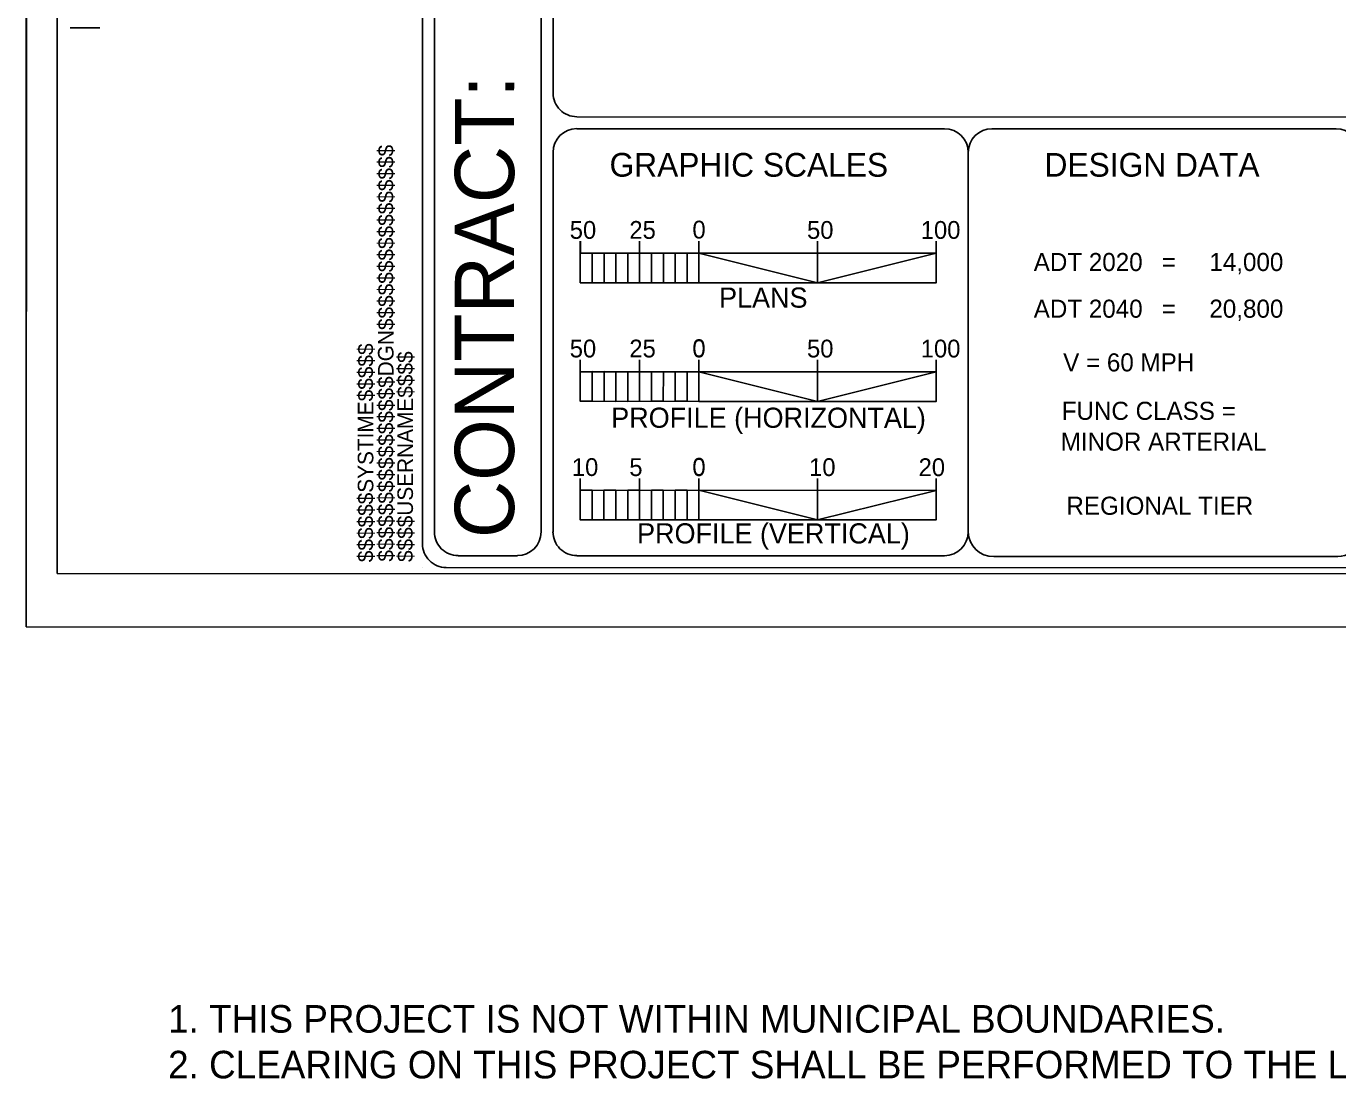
# Model space of a CAD drawing. Extents: x 2110629 to 2114002, y 669321 to 671542.
# Drawn here: x 2110629 to 2111580, y 669321 to 670084 of the extents above; entities that cross this region are included whole.
import ezdxf

# ---------------------------------------------------------------- set-up
doc = ezdxf.new("R2010")
doc.units = 0
for name, color, linetype in [('Exist Guardrail', 7, 'Continuous'), ('Exist Roads Curbs', 7, 'Continuous'), ('Exist Roads EOP Other Text', 7, 'Continuous'), ('Exist Structure Minor Catch Basin', 7, 'Continuous'), ('Exist Utilities Telephone Test Hole SUE LOS A Text', 7, 'Continuous'), ('Exist Utilities Water Test Hole SUE LOS A Text', 7, 'Continuous')]:
    doc.layers.add(name, color=color, linetype=linetype)

msp = doc.modelspace()

# ---------------------------------------------------------------- linework, layer by layer
at = {"layer": 'Exist Roads Curbs'}
for p, q in [((2110629.24, 671542.03), (2110628.92, 669648.68)), ((2110628.92, 669648.68), (2113527.5, 669648.19))]:
    msp.add_line(p, q, dxfattribs=at)
at = {"layer": 'Exist Roads EOP Other Text'}
msp.add_lwpolyline([(2110651.3, 669687.3), (2113519.77, 669686.81), (2113520.07, 671502.9), (2110651.61, 671503.39)], close=True, dxfattribs=at)
at = {"layer": 'Exist Structure Minor Catch Basin'}
for p, q in [((2111002.44, 669717.47), (2111002.74, 671473.14)), ((2111011.1, 670035.9), (2111011.35, 671473.14)), ((2110660.84, 670083.27), (2110682.35, 670083.29)), ((2110660.84, 670083.27), (2110682.35, 670083.29)), ((2111028.31, 670018.68), (2113472.49, 670018.27)), ((2111028.31, 670010.05), (2111295.1, 670010.03)), ((2111329.53, 670010), (2111579.11, 670009.98)), ((2111011.07, 669717.44), (2111011.1, 669992.86)), ((2111312.31, 669992.81), (2111312.27, 669717.39)), ((2111030.88, 669919.88), (2111030.88, 669928.47)), ((2111030.88, 669928.47), (2111030.88, 669928.47)), ((2111073.91, 669919.85), (2111073.91, 669928.48)), ((2111116.94, 669919.84), (2111116.94, 669928.45)), ((2111203, 669919.85), (2111203, 669928.44)), ((2111289.06, 669919.84), (2111289.07, 669928.44)), ((2111030.88, 669919.88), (2111030.87, 669898.36)), ((2111030.88, 669919.88), (2111030.88, 669919.88)), ((2111289.06, 669919.84), (2111030.88, 669919.88)), ((2111091.12, 669919.87), (2111091.12, 669898.35)), ((2111203, 669919.85), (2111203, 669898.34)), ((2111289.06, 669898.3), (2111289.06, 669919.84)), ((2111030.87, 669898.36), (2111289.06, 669898.3)), ((2111030.86, 669833.8), (2111030.86, 669842.42)), ((2111030.86, 669833.8), (2111030.86, 669842.42)), ((2111030.86, 669842.42), (2111030.86, 669842.42)), ((2111073.92, 669833.79), (2111073.9, 669842.42)), ((2111073.92, 669833.79), (2111073.9, 669842.42)), ((2111116.93, 669833.8), (2111116.93, 669842.39)), ((2111116.93, 669833.8), (2111116.93, 669842.39)), ((2111202.99, 669833.79), (2111202.99, 669842.4)), ((2111202.99, 669833.79), (2111202.99, 669842.4)), ((2111289.05, 669833.77), (2111289.07, 669842.38)), ((2111289.05, 669833.77), (2111289.07, 669842.38)), ((2111030.86, 669833.8), (2111030.86, 669812.3)), ((2111030.86, 669833.8), (2111030.86, 669833.8)), ((2111289.05, 669833.77), (2111030.86, 669833.8)), ((2111030.86, 669833.8), (2111030.86, 669833.8)), ((2111289.05, 669833.77), (2111030.86, 669833.8)), ((2111091.11, 669833.79), (2111091.1, 669812.29)), ((2111202.99, 669833.79), (2111202.98, 669812.27)), ((2111289.05, 669812.26), (2111289.05, 669833.77)), ((2111030.86, 669812.3), (2111289.05, 669812.26)), ((2111030.87, 669747.73), (2111030.85, 669756.36)), ((2111030.87, 669747.73), (2111030.85, 669756.36)), ((2111030.87, 669747.73), (2111030.85, 669756.36)), ((2111030.85, 669756.36), (2111030.85, 669756.36)), ((2111073.88, 669747.75), (2111073.88, 669756.33)), ((2111073.88, 669747.75), (2111073.88, 669756.33)), ((2111073.88, 669747.75), (2111073.88, 669756.33)), ((2111116.91, 669747.74), (2111116.93, 669756.33)), ((2111116.91, 669747.74), (2111116.93, 669756.33)), ((2111116.91, 669747.74), (2111116.93, 669756.33)), ((2111202.97, 669747.7), (2111202.97, 669756.33)), ((2111202.97, 669747.7), (2111202.97, 669756.33)), ((2111202.97, 669747.7), (2111202.97, 669756.33)), ((2111289.04, 669747.71), (2111289.04, 669756.3)), ((2111289.04, 669747.71), (2111289.04, 669756.3)), ((2111289.04, 669747.71), (2111289.04, 669756.3)), ((2111030.87, 669747.73), (2111030.84, 669726.24)), ((2111030.87, 669747.73), (2111030.87, 669747.73)), ((2111289.04, 669747.71), (2111030.87, 669747.73)), ((2111030.87, 669747.73), (2111030.87, 669747.73)), ((2111289.04, 669747.71), (2111030.87, 669747.73)), ((2111030.87, 669747.73), (2111030.87, 669747.73)), ((2111289.04, 669747.71), (2111030.87, 669747.73)), ((2111091.09, 669747.72), (2111091.09, 669726.21)), ((2111202.97, 669747.7), (2111202.97, 669726.19)), ((2111289.03, 669726.2), (2111289.04, 669747.71)), ((2111030.84, 669726.24), (2111289.03, 669726.2)), ((2110916.38, 669691.66), (2110916.38, 669691.66)), ((2110916.38, 669691.66), (2110916.38, 669691.66)), ((2110916.38, 669691.66), (2110916.38, 669691.66)), ((2110916.38, 669691.66), (2110916.38, 669691.66))]:
    msp.add_line(p, q, dxfattribs=at)
for points in [[(2110916.68, 671481.76), (2110916.38, 669708.87)], [(2110916.68, 671481.76), (2110916.38, 669708.87)], [(2110925.3, 671473.15), (2110924.99, 669717.48)], [(2110942.17, 669700.26), (2110985.23, 669700.26)], [(2111028.26, 669700.23), (2111295.05, 669700.2)], [(2111330.8, 669699.73), (2111580.38, 669699.68)], [(2110933.59, 669691.64), (2113481.04, 669691.21)]]:
    msp.add_lwpolyline(points, dxfattribs=at)
for points in [[(2111030.88, 669919.88), (2111039.48, 669919.88), (2111039.48, 669898.36), (2111030.87, 669898.36)], [(2111048.09, 669919.88), (2111056.7, 669919.85), (2111056.69, 669898.34), (2111048.11, 669898.34)], [(2111065.3, 669919.85), (2111073.91, 669919.85), (2111073.9, 669898.36), (2111065.3, 669898.36)], [(2111082.51, 669919.85), (2111091.12, 669919.87), (2111091.12, 669898.35), (2111082.51, 669898.36)], [(2111099.73, 669919.87), (2111108.33, 669919.87), (2111108.33, 669898.33), (2111099.72, 669898.35)], [(2111116.94, 669919.84), (2111203, 669898.34), (2111116.94, 669898.33)], [(2111289.06, 669919.84), (2111203, 669898.34), (2111289.06, 669898.3)], [(2111030.86, 669833.8), (2111039.47, 669833.82), (2111039.47, 669812.3), (2111030.86, 669812.3)], [(2111048.08, 669833.82), (2111056.68, 669833.81), (2111056.7, 669812.28), (2111048.07, 669812.3)], [(2111065.29, 669833.81), (2111073.92, 669833.79), (2111073.89, 669812.3), (2111065.28, 669812.28)], [(2111082.5, 669833.79), (2111091.11, 669833.79), (2111091.1, 669812.29), (2111082.5, 669812.29)], [(2111099.71, 669833.81), (2111108.32, 669833.81), (2111108.32, 669812.29), (2111099.71, 669812.29)], [(2111116.93, 669833.8), (2111202.98, 669812.27), (2111116.92, 669812.27)], [(2111289.05, 669833.77), (2111202.98, 669812.27), (2111289.05, 669812.26)], [(2111030.87, 669747.73), (2111039.45, 669747.73), (2111039.45, 669726.22), (2111030.84, 669726.24)], [(2111048.06, 669747.75), (2111056.67, 669747.75), (2111056.66, 669726.24), (2111048.06, 669726.24)], [(2111065.27, 669747.75), (2111073.88, 669747.75), (2111073.88, 669726.21), (2111065.27, 669726.23)], [(2111082.51, 669747.73), (2111091.09, 669747.72), (2111091.09, 669726.21), (2111082.48, 669726.23)], [(2111099.7, 669747.72), (2111108.3, 669747.74), (2111108.3, 669726.23), (2111099.69, 669726.23)], [(2111116.91, 669747.74), (2111202.97, 669726.19), (2111116.91, 669726.23)], [(2111289.04, 669747.71), (2111202.97, 669726.19), (2111289.03, 669726.2)]]:
    msp.add_lwpolyline(points, close=True, dxfattribs=at)
for centre, radius, start, end in [((2111028.32, 670035.97), 17.21, 179.9903, 269.9903), ((2111028.31, 669992.94), 17.21, 89.9903, 179.9903), ((2111295.11, 669992.89), 17.21, 359.9903, 89.9903), ((2111329.53, 669992.89), 17.21, 89.9903, 179.9903), ((2111579.11, 669992.85), 17.21, 359.9903, 89.9903), ((2110942.21, 669717.55), 17.21, 179.9903, 269.9903), ((2110985.24, 669717.55), 17.21, 269.9903, 359.9903), ((2111028.27, 669717.54), 17.21, 179.9903, 269.9903), ((2111295.06, 669717.49), 17.21, 269.9903, 359.9903), ((2111330.42, 669717.87), 18.15, 181.2031, 271.2031), ((2110933.6, 669708.95), 17.21, 179.9903, 269.9903), ((2111580.39, 669716.9), 17.21, 269.9903, 337.36921)]:
    msp.add_arc(centre, radius, start, end, dxfattribs=at)
at = {"layer": 'Exist Utilities Telephone Test Hole SUE LOS A Text'}
for p, q in [((2111030.9, 669919.9), (2111030.9, 669928.49)), ((2111073.93, 669919.87), (2111073.93, 669928.48)), ((2111203.02, 669919.87), (2111203.03, 669928.46)), ((2111289.09, 669919.84), (2111289.09, 669928.46)), ((2110916.4, 669691.66), (2110916.4, 669691.66))]:
    msp.add_line(p, q, dxfattribs=at)
at = {"layer": 'Exist Utilities Water Test Hole SUE LOS A Text'}
msp.add_lwpolyline([(2113527.82, 671541.54), (2110629.24, 671542.03), (2110628.92, 669648.68), (2113527.5, 669648.19)], close=True, dxfattribs=at)

# ---------------------------------------------------------------- texts
at = {"layer": 'Exist Guardrail'}
for s, p in [('1. THIS PROJECT IS NOT WITHIN MUNICIPAL BOUNDARIES.', (2110731.83, 669354.22)), ('2. CLEARING ON THIS PROJECT SHALL BE PERFORMED TO THE LIMITS ESTABLISHED BY METHOD II.', (2110731.83, 669321.04))]:
    msp.add_text(s, height=20, dxfattribs=at).set_placement(p)
at = {"layer": 'Exist Structure Minor Catch Basin'}
for s, height, rotation, p in [('CONTRACT:', 43.031, 89.9903, (2110982.84, 669713.1)), ('$$$$$$$$$$$$$$$$DGN$$$$$$$$$$$$$$$$', 11.2957, 89.9903, (2110895.36, 669695.99)), ('GRAPHIC SCALES', 17.2118, 359.9903, (2111052.08, 669975.3)), ('DESIGN DATA', 17.2118, 359.9903, (2111367.65, 669975.31)), ('0', 12.91, 359.9903, (2111112.21, 669930.43)), ('PLANS', 14.63, 359.9903, (2111131.56, 669880.25)), ('$$$$$$SYSTIME$$$$$', 11.2957, 89.9903, (2110880.72, 669695.56)), ('0', 12.91, 359.9903, (2111112.19, 669844.39)), ('0', 12.91, 359.9903, (2111112.19, 669844.13)), ('$$$$USERNAME$$$$', 11.2957, 89.9903, (2110909.47, 669695.69)), ('PROFILE (HORIZONTAL)', 14.6299, 359.9903, (2111053.32, 669793.09)), ('0', 12.91, 359.9903, (2111112.18, 669758.33)), ('0', 12.91, 359.9903, (2111112.18, 669758.07)), ('0', 12.91, 359.9903, (2111112.18, 669758.07)), ('PROFILE (VERTICAL)', 14.6299, 359.9903, (2111072.07, 669709.17))]:
    msp.add_text(s, height=height, rotation=rotation, dxfattribs=at).set_placement(p)
at = {"layer": 'Exist Utilities Telephone Test Hole SUE LOS A Text'}
for s, height, rotation, p in [('50', 12.909, 359.9903, (2111023.22, 669930.21)), ('25', 12.909, 359.9903, (2111066.46, 669930.2)), ('50', 12.909, 359.9903, (2111195.35, 669930.18)), ('100', 12.909, 359.9903, (2111277.85, 669930.19)), ('ADT 2020', 13.125, 360, (2111359.81, 669906.81)), ('=', 13.13, 360, (2111452.74, 669906.89)), ('14,000   ', 13.125, 360, (2111487.22, 669906.83)), ('ADT 2040', 13.125, 360, (2111359.81, 669872.94)), ('=', 13.13, 360, (2111452.74, 669873.02)), ('20,800   ', 13.125, 360, (2111487.22, 669872.96)), ('50', 12.909, 359.9903, (2111023.21, 669844.15)), ('25', 12.909, 359.9903, (2111066.44, 669844.16)), ('50', 12.909, 359.9903, (2111195.33, 669844.12)), ('100', 12.909, 359.9903, (2111277.84, 669844.13)), ('V = 60 MPH', 13.125, 360, (2111381.17, 669833.98)), ('FUNC CLASS =', 13.125, 360, (2111380.1, 669798.85)), ('MINOR ARTERIAL', 13.125, 360, (2111379.38, 669776.5)), ('10', 12.909, 359.9903, (2111024.74, 669758.11)), ('5 ', 12.909, 359.9903, (2111066.43, 669758.1)), ('10', 12.909, 359.9903, (2111196.84, 669758.08)), ('20 ', 12.909, 359.9903, (2111276.28, 669758.04)), ('REGIONAL TIER', 13.125, 360, (2111383.52, 669729.98))]:
    msp.add_text(s, height=height, rotation=rotation, dxfattribs=at).set_placement(p)

doc.saveas('drawing.dxf')
